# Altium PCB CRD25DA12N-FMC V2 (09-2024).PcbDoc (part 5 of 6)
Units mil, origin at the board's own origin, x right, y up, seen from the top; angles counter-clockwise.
Board outline 8000 x 8000 mil, 6 copper layers (Top Layer, Layer 2, Layer 3, Layer 4, Layer 5, Bottom Layer), stack 91 mil thick; 602 components, 333 nets, 1670 pads, 639 vias.
Unrouted connection lines stored in the file: 1.
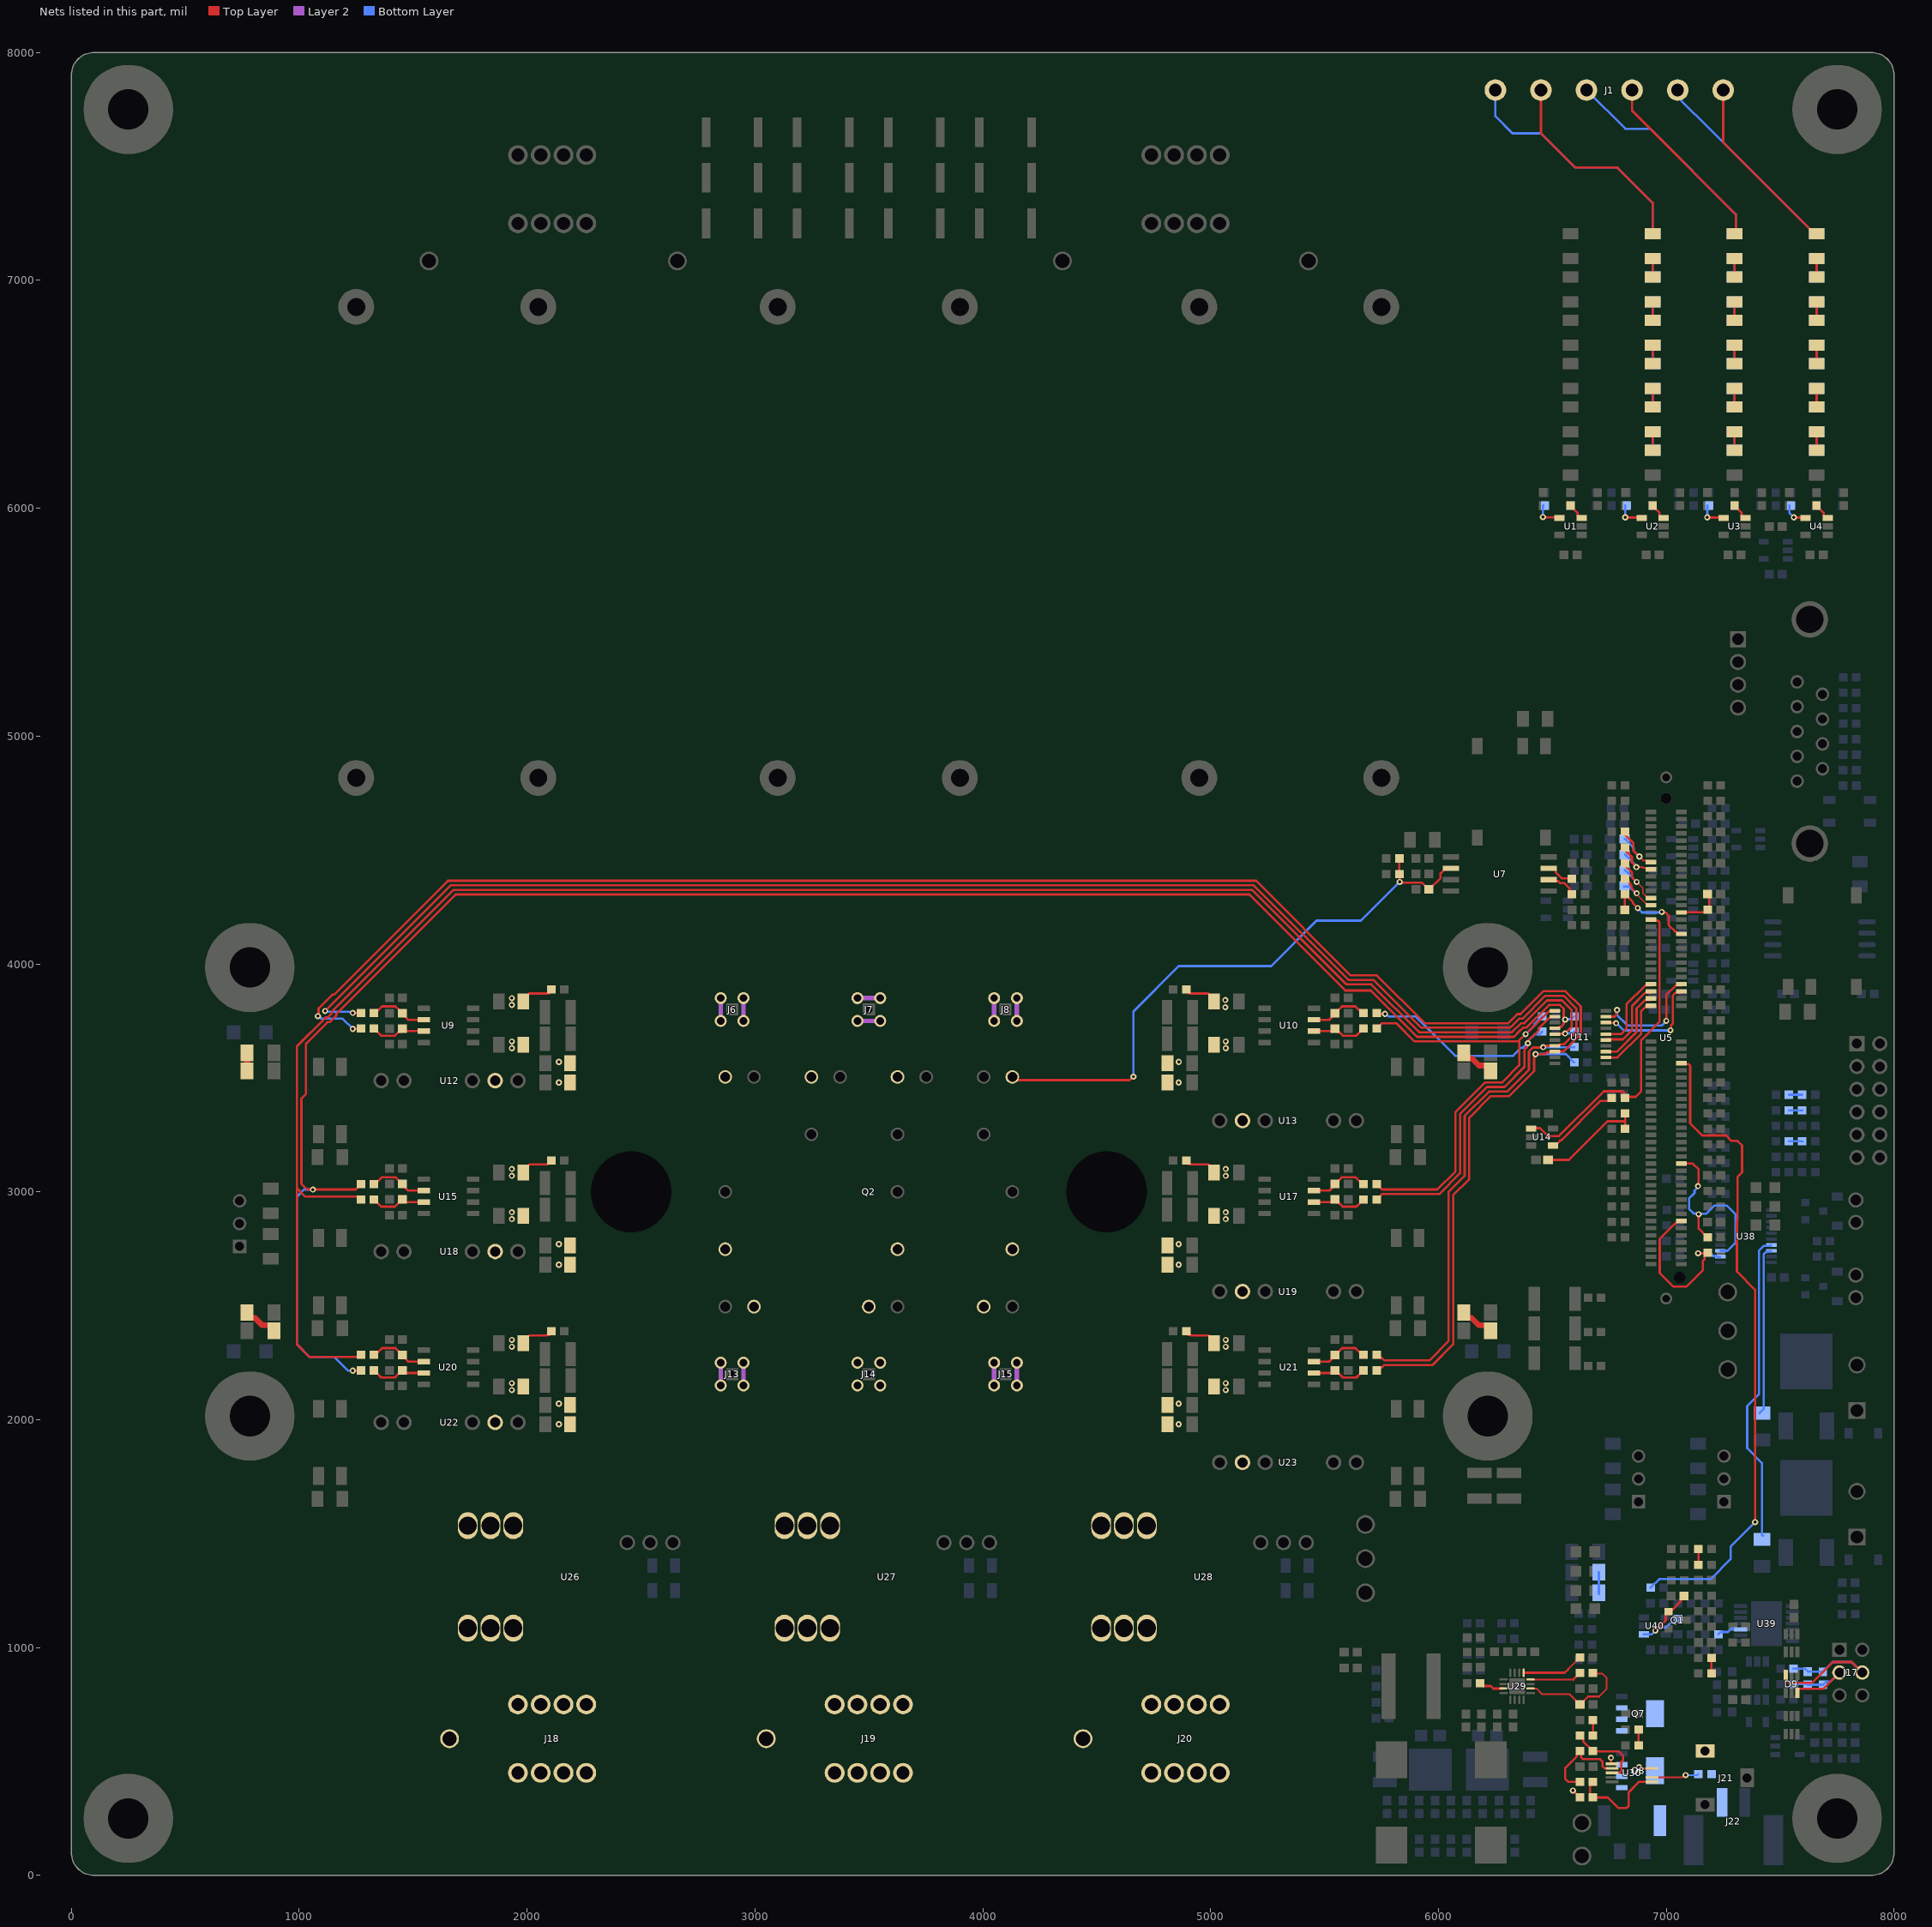
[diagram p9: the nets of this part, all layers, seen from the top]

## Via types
v1: diameter 27, hole 13, Top Layer to Bottom Layer, tented both sides, 543 vias
v2: diameter 50, hole 28, Top Layer to Bottom Layer, tented both sides, 76 vias
v3: diameter 19.68, hole 7.87, Top Layer to Bottom Layer, tented top, 15 vias
v4: diameter 19.68, hole 7.87, Top Layer to Bottom Layer, tented both sides, 5 vias

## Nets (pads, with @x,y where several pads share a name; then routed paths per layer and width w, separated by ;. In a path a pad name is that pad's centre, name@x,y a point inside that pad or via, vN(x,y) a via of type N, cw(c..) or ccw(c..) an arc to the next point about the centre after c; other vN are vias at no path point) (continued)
NetR14_2: R14.2 R18.1 | length 79.8
  Top Layer w10: R18.1@6940,7015.12 R14.2@6940,7094.88
NetR15_2: R15.2 R19.1 | length 79.8
  Top Layer w10: R19.1@7300,7015.12 R15.2@7300,7094.88
NetR16_2: R16.2 R20.1 | length 79.8
  Top Layer w10: R20.1@7660,7015.12 R16.2@7660,7094.88
NetR18_2: R18.2 R22.1 | length 79.8
  Top Layer w10: R22.1@6940,6825.12 R18.2@6940,6904.88
NetR19_2: R19.2 R23.1 | length 79.8
  Top Layer w10: R23.1@7300,6825.12 R19.2@7300,6904.88
NetR20_2: R20.2 R24.1 | length 79.8
  Top Layer w10: R24.1@7660,6825.12 R20.2@7660,6904.88
NetR22_2: R22.2 R26.1 | length 79.8
  Top Layer w10: R26.1@6940,6635.12 R22.2@6940,6714.88
NetR23_2: R23.2 R27.1 | length 79.8
  Top Layer w10: R27.1@7300,6635.12 R23.2@7300,6714.88
NetR24_2: R24.2 R28.1 | length 79.8
  Top Layer w10: R28.1@7660,6635.12 R24.2@7660,6714.88
NetR26_2: R26.2 R30.1 | length 79.8
  Top Layer w10: R30.1@6940,6445.12 R26.2@6940,6524.88
NetR27_2: R27.2 R31.1 | length 79.8
  Top Layer w10: R31.1@7300,6445.12 R27.2@7300,6524.88
NetR28_2: R28.2 R32.1 | length 79.8
  Top Layer w10: R32.1@7660,6445.12 R28.2@7660,6524.88
NetR30_2: R30.2 R34.1 | length 79.8
  Top Layer w10: R34.1@6940,6255.12 R30.2@6940,6334.88
NetR31_2: R31.2 R35.1 | length 79.8
  Top Layer w10: R35.1@7300,6255.12 R31.2@7300,6334.88
NetR32_2: R32.2 R36.1 | length 79.8
  Top Layer w10: R36.1@7660,6255.12 R32.2@7660,6334.88
NetR37_2: R37.2 U1.3 | length 79.1
  Top Layer w10: R37.2@6580,6011.38 6580,6010.47 6610.59,5979.88 6610.59,5966.18 6619.37,5957.4 U1.3@6628.23,5957.4
NetR39_2: R39.2 U2.3 | length 84.1
  Top Layer w10: R39.2@6940,6011.38 6940,6010.47 6970.59,5979.88 6970.59,5961.18 6979.37,5952.4 U2.3@6988.23,5952.4
NetR41_2: R41.2 U3.3 | length 79.1
  Top Layer w10: R41.2@7300,6011.38 7300,6010.47 7330.59,5979.88 7330.59,5966.18 7339.37,5957.4 U3.3@7348.23,5957.4
NetR43_2: R43.2 U4.3 | length 79.1
  Top Layer w10: R43.2@7660,6011.38 7660,6010.47 7690.59,5979.88 7690.59,5966.18 7699.37,5957.4 U4.3@7708.23,5957.4
NetR56_2: R56.2 U7.7 | length 122.2
  Top Layer w10: U7.7@6484.57,4420 6508.19,4420 6515,4413.19 6515,4402.37 6542.37,4375 6580.38,4375 R56.2@6581.38,4374
NetR58_2: R58.2 U7.6 | length 137.2
  Top Layer w10: U7.6@6484.57,4370 6491.38,4363.19 6525.89,4363.19 6534.08,4355 6552.56,4355 6574.96,4332.61 6574.96,4317.42 R58.2@6586.38,4306
NetR77_1: R77.1 R80.2 | length 81.7
  Top Layer w25: R80.2@770.9,3530 770.9,3605.9 R77.1@775,3610
NetR78_1: R78.1 R81.2 | length 158.9
  Top Layer w25: R78.1@6110.9,3610 6110.9,3602.08 6127.05,3585.92 6146.37,3585.92 6178.22,3554.08 6212.95,3554.08 6225,3542.03 R81.2@6225,3530
NetR85_2: R85.2 U14.4 | length 335.2
  Top Layer w10: U14.4@6512.09,3204.6 6514.09,3204.6 6534.49,3225 6538.28,3225 6712.33,3399.04 6748.42,3399.04 R85.2@6761.38,3412
NetR86_1: R86.1 R88.1 R91.1 | length 477.1
  Top Layer w10: R91.1@6481.62,3140 6573.01,3140 6742.32,3309.31 6820,3309.31 ; R86.1@6818.62,3344 6820,3342.62 6820,3309.31 ; R88.1@6820,3276 6820,3309.31
NetR115_2: R115.2 R118.1 | length 163.1
  Top Layer w25: R115.2@770.9,2470 770.9,2462.08 787.05,2445.92 806.37,2445.92 838.22,2414.08 872.95,2414.08 895,2392.03 R118.1@895,2390
NetR116_1: R116.1 R119.2 | length 159.8
  Top Layer w25: R116.1@6110.9,2470 6110.9,2462.08 6127.05,2445.92 6146.37,2445.92 6178.22,2414.08 6215.92,2414.08 R119.2@6235,2395
NetR136_2: R136.2 R137.1 | length 69
  Top Layer w10: R137.1@7141.38,1363 R136.2@7141.38,1432
NetR145_2: R145.2 U29.5 | length 274.5
  Top Layer w8: 6569.74,905.26 6620.47,956 R145.2@6621.38,956
  Top Layer w10: U29.5@6374.53,889.23 6553.71,889.23 6569.74,905.26
NetR146_1: R146.1 R148.2 | length 68
  Top Layer w10: R148.2@7198.62,886 R146.1@7198.62,954
NetR147_1: R147.1 U29.4 | length 228.9
  Top Layer w8: U29.4@6404.23,859.53 6592,859.53
  Top Layer w10: 6592,859.53 6620.47,888 R147.1@6621.38,888
NetR149_2: R149.2 U29.11 | length 112.3
  Top Layer w10: R149.2@6183.62,844 6196.58,831.04 6229.48,831.04 6240.69,819.84 6264.04,819.84 6285.48,819.87 U29.11@6285.77,820.16
NetR150_2: R150.2 R152.1 | length 72.5
  Top Layer w10: R150.2@6675,685 6678.62,681.38 R152.1@6678.62,614
NetR151_2: R151.2 R153.1 | length 70
  Top Layer w10: R153.1@6878.62,570 R151.2@6878.62,640
NetR152_2: R152.2 R154.1 U30.3 | length 348.4
  Top Layer w8: U30.3@6761.17,449.69 6795,449.69
  Top Layer w10: R152.2@6621.38,614 6622.28,614 6635.24,601.04 6635.24,588.48 6677.72,546 R154.1@6678.62,546 6679.94,544.68 6769.2,544.68 6770.38,543.5 6791.81,543.5 6810,525.31 6810,505 6803.1,498.1 6803.1,458.1 6795,450 6795,449.69
NetR154_2: R154.2 R155.1 U30.2 | length 418.9
  Top Layer w8: 6730,469.69 U30.2@6762.91,469.69
  Top Layer w10: R155.1@6621.38,410 6570,410 6556.5,423.5 6556.5,471.5 6580,495 6607.52,522.52 6607.52,533.04 R154.2@6620.47,546 ; R154.2@6621.38,546 R154.2@6620.47,546 ; 6730,469.69 6720,479.69 6720,500 6710,510 6635,510 6626.1,518.9 6626.1,536.38 6626.1,540.38 R154.2@6620.47,546
NetR155_2: R155.2 R156.1 U30.6 | length 442.1
  Top Layer w10: R156.1@6678.62,342 6743,342 6790,295 6825.31,295 6835,304.69 6835,365 6880.63,410.63 U30.6@6937.09,410.63 ; R155.2@6678.62,410 6677.96,410 6665,397.04 6665,354.96 6677.96,342 R156.1@6679.53,342
NetR157_2: R157.2 R161.1 | length 79.8
  Bottom Layer w10: R161.1@7660,7015.12 R157.2@7660,7094.88
NetR158_2: R158.2 R162.1 | length 79.8
  Bottom Layer w10: R162.1@7300,7015.12 R158.2@7300,7094.88
NetR159_2: R159.2 R163.1 | length 79.8
  Bottom Layer w10: R163.1@6940,7015.12 R159.2@6940,7094.88
NetR161_2: R161.2 R165.1 | length 79.8
  Bottom Layer w10: R165.1@7660,6825.12 R161.2@7660,6904.88
NetR162_2: R162.2 R166.1 | length 79.8
  Bottom Layer w10: R166.1@7300,6825.12 R162.2@7300,6904.88
NetR163_2: R163.2 R167.1 | length 79.8
  Bottom Layer w10: R167.1@6940,6825.12 R163.2@6940,6904.88
NetR165_2: R165.2 R169.1 | length 79.8
  Bottom Layer w10: R169.1@7660,6635.12 R165.2@7660,6714.88
NetR166_2: R166.2 R170.1 | length 79.8
  Bottom Layer w10: R170.1@7300,6635.12 R166.2@7300,6714.88
NetR167_2: R167.2 R171.1 | length 79.8
  Bottom Layer w10: R171.1@6940,6635.12 R167.2@6940,6714.88
NetR169_2: R169.2 R173.1 | length 79.8
  Bottom Layer w10: R173.1@7660,6445.12 R169.2@7660,6524.88
NetR170_2: R170.2 R174.1 | length 79.8
  Bottom Layer w10: R174.1@7300,6445.12 R170.2@7300,6524.88
NetR171_2: R171.2 R175.1 | length 79.8
  Bottom Layer w10: R175.1@6940,6445.12 R171.2@6940,6524.88
NetR173_2: R173.2 R177.1 | length 79.8
  Bottom Layer w10: R177.1@7660,6255.12 R173.2@7660,6334.88
NetR174_2: R174.2 R178.1 | length 79.8
  Bottom Layer w10: R178.1@7300,6255.12 R174.2@7300,6334.88
NetR175_2: R175.2 R179.1 | length 79.8
  Bottom Layer w10: R179.1@6940,6255.12 R175.2@6940,6334.88
NetR182_2: R182.2 U4.4 | length 112.5
  Top Layer w10: v1(7560,5960) 7561.3,5958.7 7610.47,5958.7 U4.4@7611.77,5957.4
  Bottom Layer w10: R182.2@7540,6011.38 7540,5980 v1(7560,5960)
NetR185_2: R185.2 U3.4 | length 124.2
  Top Layer w10: v1(7180,5960) 7181.3,5958.7 7250.47,5958.7 U3.4@7251.77,5957.4
  Bottom Layer w10: v1(7180,5960) R185.2@7180,6011.38
NetR188_2: R188.2 U2.4 | length 124.2
  Top Layer w10: v1(6820,5960) 6821.3,5958.7 6890.47,5958.7 U2.4@6891.77,5957.4
  Bottom Layer w10: v1(6820,5960) R188.2@6820,6011.38
NetR191_2: R191.2 U1.4 | length 125.4
  Top Layer w10: v1(6458.58,5961.42) 6460.59,5959.41 6529.76,5959.41 U1.4@6531.77,5957.4
  Bottom Layer w10: v1(6458.58,5961.42) 6458.58,6009.96 R191.2@6460,6011.38
NetR221_2: R221.2 R222.1 | length 57.8
  Bottom Layer w10: R222.1@7538.62,3426 R221.2@7596.38,3426
NetR224_2: R224.2 R225.1 | length 57.8
  Bottom Layer w10: R225.1@7538.62,3358 R224.2@7596.38,3358
NetR230_2: R230.2 R231.1 | length 62.2
  Bottom Layer w8: R231.1@7538.62,3222 R230.2@7596.38,3222 7598,3222 R230.2@7600,3220
NetR246_1: R246.1 R248.2 | length 95.4
  Bottom Layer w10: R246.1@6704.1,1330 R248.2@6704.1,1240 6704.1,1235.9 R248.2@6705,1235
NetR257_1: R257.1 U39.3 | length 76.6
  Bottom Layer w10: R257.1@7228.62,1058 7238.6,1067.98 7271.26,1067.98 7286.55,1083.27 7294.76,1083.27
NetR275_1: R275.1 U30.7 | length 210.4
  Top Layer w8: U30.7@6937.09,430.32 7070.17,430.32 7079.86,440 v1(7085,440)
  Bottom Layer w8: v1(7085,440) 7136.38,440 R275.1@7141.38,445
NTC1: C18.1 Q2.NTC2 R53.1 R55.2 U7.2 | length 2627.4
  Top Layer w10: Q2.NTC2@4129.92,3503.94 4143.45,3503.94 4157.39,3490 4645.4,3490 4660.4,3505 v1(4661.5,3505) ; R53.1@5828.62,4463 R55.2@5828.62,4395 5830,4393.62 v1(5830,4360) 5833.14,4356.86 5927.76,4356.86 5957.63,4327 C18.1@5958.58,4327 5959.53,4327 6009,4376.47 6009,4397.19 6031.81,4420 U7.2@6055.43,4420
  Bottom Layer w10: v1(4661.5,3505) 4661.5,3791.5 4860.75,3990.75 5265.75,3990.75 5465,4190 5660,4190 v1(5830,4360)
NTC_ISO: C21.1 R59.2 U5.36 | length 414.7
  Top Layer w10: C21.1@6818.58,4240 R59.2@6818.62,4306 R59.2@6818.62,4306 6819.53,4306 6854.08,4271.45 6854.08,4265.92 v1(6875,4245) ; v1(6980.19,4228.29) 6984.79,4228.29 6988.08,4225 6997.19,4225 7011.1,4211.09 7011.1,4170 7038.75,4142.35 7042.5,4142.35 7053.15,4131.69 U5.36@7066.93,4131.69
  Bottom Layer w10: v1(6875,4245) 6893.91,4226.09 v1@6980.19,4226.09
RELAY1: R244.1 U38.17 | length 1364.6
  Bottom Layer w10: R244.1@7425,1490 7420,1495 7420,1810 7355,1875 7355,2060 7407.58,2112.58 7407.58,2742.42 7428.03,2762.87 7456.69,2762.87 U38.17@7459.41,2765.59
RELAY1_OUT: R111.2 U5.92 U38.3 | length 847.1
  Top Layer w10: U5.92@7066.93,3123.82 7116.18,3123.82 7141.99,3098.01 7141.99,3027.86 v1(7139.23,3025.1) ; v1(7142.17,2901.43) 7141.81,2901.06 7141.81,2838.67 7180.47,2800 R111.2@7181.38,2800
  Bottom Layer w10: v1(7139.23,3025.1) 7139.23,3020.5 7123.63,3004.91 7123.63,2993.33 7121.81,2991.5 7120.99,2991.5 7099.95,2970.46 7099.95,2924.75 7120.02,2904.68 7138.92,2904.68 v1(7142.17,2901.43) ; v1@7142.17,2900 7146.1,2903.93 7175.67,2903.93 7211.9,2940.16 7264.84,2940.16 7304.04,2900.96 7304.04,2777.07 7267.99,2741.02 U38.3@7237.8,2741.02
RELAY2: R243.1 U38.18 | length 742.2
  Bottom Layer w10: R243.1@7410,2029.1 7427.58,2046.69 7427.58,2726.71 7435.18,2734.31 7439.74,2734.31 7443.58,2738.15 7457.56,2738.15 U38.18@7459.41,2740
RELAY2_OUT: R112.2 U5.108 U38.2 | length 744.3
  Top Layer w10: U5.108@7066.93,2871.85 7053.15,2871.85 7042.5,2861.2 7038.75,2861.2 6971.5,2793.95 6971.5,2643.5 7031.18,2583.82 7088.82,2583.82 7160,2655 7160,2695.31 7167.52,2702.82 7167.52,2719.04 R112.2@7178.47,2730 ; v1(7140,2730) R112.2@7178.47,2730 ; R112.2@7179.38,2730 R112.2@7178.47,2730
  Bottom Layer w10: v1(7140,2730) 7194.6,2730 7206.29,2718.31 7219.17,2718.31 7223.07,2714.41 U38.2@7235,2714.41
RSLV_PWM: R247.1 U5.64 | length 2869.7
  Top Layer w10: U5.64@7066.93,3564.76 7071.69,3560 7098.75,3560 7105,3553.75 7105,3300.01 7157.96,3247.04 7262.96,3247.04 7286.5,3223.5 7312.79,3223.5 7332.57,3203.72 7332.57,3085.27 7313.5,3066.21 7313.5,2877.28 7310,2873.78 7310,2650 7390,2570 v1(7390,1550)
  Bottom Layer w10: R247.1@6931.38,1263 6932.28,1263 6969.17,1299.89 7194.89,1299.89 7282.19,1387.19 7282.19,1442.19 v1(7390,1550)
RSLV_PWM_FILT: C91.1 Q1.1 R253.2 U40.1 | length 383.9
  Top Layer w10: v1(6952.26,1074.16) 6997.91,1119.81 6997.91,1146.65 7008.66,1157.4 Q1.1@7010.63,1157.4 ; Q1.1@7015.63,1157.4 7017.6,1157.4 7063.76,1203.57 7063.76,1213.14 7077.63,1227 C91.1@7078.58,1227
  Bottom Layer w10: U40.1@6901.77,1057.6 6935.7,1057.6 v1(6952.26,1074.16) 6956.86,1074.16 6970.8,1088.1 7000.44,1088.1 7019.3,1106.96 7031.43,1106.96 7050.47,1126 R253.2@7051.38,1126
S1: C51.1 C59.2 C65.1 C67.2 J6.2 J6.3 J6.4 J6.5 Q2.S1 R94.1 U18.6 | length 346.1
  Top Layer w10: C51.1@1984.19,3085 1984.19,3093.91 2010.28,3120 2087.47,3120 2097.47,3130 R94.1@2106.38,3130
  Layer 2 w20: J6.4@2850,3750 J6.2@2850,3850 ; J6.5@2950,3750 J6.3@2950,3850
  other v1: 2140,2680 2140,2770 1933.37,2880 1933.37,2910 1933.37,3070 1933.37,3100
S2: C73.1 C79.2 C83.1 C85.2 J13.2 J13.3 J13.4 J13.5 Q2.S2 R120.1 U22.6 | length 346.1
  Top Layer w10: C73.1@1984.19,2335 1984.19,2343.91 2010.28,2370 2086.66,2370 2088.7,2372.04 2098.42,2372.04 R120.1@2106.38,2380
  Layer 2 w20: J13.4@2850,2150 J13.2@2850,2250 ; J13.5@2950,2150 J13.3@2950,2250
  other v1: 2140,1980 2140,2070 1933.37,2130 1933.37,2160 1933.37,2320 1933.37,2350
S3: C28.1 C36.2 C40.1 C42.2 J7.2 J7.3 J7.4 J7.5 Q2.S3 R64.1 U12.6 | length 346.1
  Top Layer w10: C28.1@1984.19,3835 1984.19,3843.91 2010.28,3870 2086.66,3870 2088.7,3872.04 2098.42,3872.04 R64.1@2106.38,3880
  Layer 2 w20: J7.4@3450,3750 J7.5@3550,3750 ; J7.2@3450,3850 J7.3@3550,3850
  other v1: 2140,3480 2140,3570 1933.37,3630 1933.37,3660 1933.37,3820 1933.37,3850
S4: C74.2 C80.1 C84.1 C86.2 J14.2 J14.3 J14.4 J14.5 Q2.S4 R121.1 U23.6 | length 146.1
  Top Layer w10: R121.1@4893.62,2380 4901.58,2372.04 4911.3,2372.04 4913.34,2370 4989.72,2370 5015.81,2343.91 C74.2@5015.81,2335
  other v1: 4860,1980 4860,2070 5066.63,2130 5066.63,2160 5066.63,2320 5066.63,2350
S5: C29.2 C37.1 C41.1 C43.2 J8.2 J8.3 J8.4 J8.5 Q2.S5 R65.1 U13.6 | length 346.1
  Top Layer w10: R65.1@4893.62,3880 4901.58,3872.04 4911.3,3872.04 4913.34,3870 4989.72,3870 5015.81,3843.91 C29.2@5015.81,3835
  Layer 2 w20: J8.4@4050,3750 J8.2@4050,3850 ; J8.5@4150,3750 J8.3@4150,3850
  other v1: 4860,3480 4860.39,3569.95 5066.63,3630 5066.63,3660 5065,3810 5065,3841.5
S6: C52.2 C60.1 C66.1 C68.2 J15.2 J15.3 J15.4 J15.5 Q2.S6 R95.1 U19.6 | length 346.1
  Top Layer w10: R95.1@4893.62,3130 4901.58,3122.04 4911.3,3122.04 4913.34,3120 4989.72,3120 5015.81,3093.91 C52.2@5015.81,3085
  Layer 2 w20: J15.4@4050,2150 J15.2@4050,2250 ; J15.5@4150,2150 J15.3@4150,2250
  other v1: 4860,2680 4860,2770 5066.63,2880 5066.63,2910 5066.63,3070 5066.63,3100
SIN: C19.1 R60.2 U5.30 | length 184.6
  Top Layer w10: U5.30@7066.93,4226.18 7171.56,4226.18 R60.2@7181.38,4236 ; R60.2@7187.44,4240 7188.72,4241.28 7188.72,4303.72 C19.1@7190,4305
SIN_N: C173.2 D9.6 J17.4 R264.1 R265.1 | length 767.9
  Top Layer w10: D9.6@7524.41,879.37 7528.27,875.51 7528.27,854.05 7536.59,845.73 7640.73,845.73 7731.5,936.5 7813.5,936.5 J17.4@7860,890
  Bottom Layer w10: R264.1@7558.62,907 7609.53,907 C173.2@7622,894.53 ; C173.2@7622,893.58 7689.96,893.58 R265.1@7689.96,896.48 ; R265.1@7688,893.62 7688,894.53 R265.1@7689.96,896.48 ; J17.4@7860,890 7813.5,936.5 7729.97,936.5 R265.1@7689.96,896.48
SIN_P: C173.1 D9.3 J17.3 R265.2 R267.1 | length 454.7
  Top Layer w10: D9.3@7575.59,800.63 7575.59,814.41 7579.45,818.27 7688.27,818.27 J17.3@7760,890
  Bottom Layer w10: R267.1@7558.62,839 7619.42,839 7622,836.42 R265.2@7688,836.38 7688,837.28 7700.96,850.24 7720.24,850.24 J17.3@7760,890
T_AMB: R85.1 U5.31 U14.1 | length 1431.3
  Top Layer w10: U14.1@6406.77,3279.4 6445.6,3279.4 6480,3245 6530,3245 6725.96,3440.96 6809.04,3440.96 6815,3435 6815,3415.62 R85.1@6818.62,3412 6823.39,3416.76 6865.74,3416.76 6890,3441.02 6890,3665.2 6970,3745.2 6970,4183.75 6963.75,4190 6937.76,4190 U5.31@6933.07,4194.68
U: Q2.U U26.4 U26.5 U26.6
U_HS: R99.1 R129.1 R214.2 U11.14 | length 8252.6
  Top Layer w10: v1(1235,2215) 1270.38,2215 R129.1@1271.38,2216 ; R99.1@1271.38,3034 1270.47,3034 1257.52,3021.04 1257.52,3020.14 1247.38,3010 v1(1060,3010) 1035,3010 1010,3035 1010,3410 1030,3430 1030,3650 1124.69,3744.69 1133.59,3744.69 1162,3773.11 1162,3780.43 1686.57,4305 5170,4305 5591.64,3883.36 5703.36,3883.36 5906.72,3680 6331.11,3680 6355.11,3704 6371.11,3720 6385.17,3720 6485.17,3820 6533.43,3820 6550,3803.43 v1@6550,3755 ; U11.14@6510.59,3717.36 6526.34,3717.36 6533.06,3724.08 6537.62,3724.08 6550,3736.46 v1@6550,3755 ; v1(6556.77,3755.76) 6550.76,3755.76 v1@6550,3755
  Bottom Layer w10: v1(1060,3010) 1021.65,3010 990,2978.35 990,2330 1045,2275 1155,2275 1215,2215 v1(1235,2215) ; v1(6556.77,3755.76) 6558.05,3757.04 6583.42,3757.04 R214.2@6596.38,3770
U_HS+_FILT: C54.1 R99.2 U15.2 | length 256.7
  Top Layer w10: R99.2@1328.62,3034 1341.58,3046.96 1346.96,3046.96 1363.86,3063.86 1422.76,3063.86 1438.76,3047.86 1449.53,3037.1 1449.53,3034 1478.53,3005 U15.2@1546.73,3005
U_HS-_FILT: C77.1 R129.2 U20.3 | length 258
  Top Layer w10: R129.2@1328.62,2216 1329.53,2216 1342.48,2203.04 1342.48,2202.52 1360,2185 1420,2185 1437.14,2202.14 1447.14,2202.14 1453.58,2208.58 C77.1@1453.58,2216 ; C77.1@1448.58,2216 1454.79,2209.79 1459.58,2205 U20.3@1546.73,2205
U_HS_PWM: U5.49 U11.6 | length 353.2
  Top Layer w10: U11.6@6735,3691.77 6801.77,3691.77 6825,3715 6825,3822.63 6906.98,3904.61 6930.16,3904.61 U5.49@6935,3909.45
U_LS: R103.1 R126.1 R216.2 U11.15 | length 8340.8
  Top Layer w10: R126.1@1271.38,2284 1262.38,2275 1045,2275 990,2330 990,3015 ; R103.1@1271.38,2966 1258.42,2978.96 1026.04,2978.96 990,3015 ; U11.15@6510.59,3691.77 6512.2,3693.39 6554.37,3693.39 6585.27,3724.28 6585.27,3796.45 6541.72,3840 6476.89,3840 6376.89,3740 6362.82,3740 6322.82,3700 5915,3700 5705,3910 5596.72,3910 5181.72,4325 1678.28,4325 1142,3788.72 1142,3781.39 1125.31,3764.69 1116.41,3764.69 990,3638.28 990,3015
  Bottom Layer w10: v1(6555.98,3695) 6588.38,3695 R216.2@6596.38,3703
U_LS+_FILT: C75.1 R126.2 U20.2 | length 256.7
  Top Layer w10: R126.2@1328.62,2284 1341.58,2296.96 1346.96,2296.96 1363.86,2313.86 1422.76,2313.86 1438.76,2297.86 1449.53,2287.1 1449.53,2284 1478.53,2255 U20.2@1546.73,2255
U_LS-_FILT: C57.1 R103.2 U15.3 | length 258
  Top Layer w10: R103.2@1328.62,2966 1329.53,2966 1342.48,2953.04 1342.48,2952.52 1360,2935 1420,2935 1437.14,2952.14 1447.14,2952.14 1453.58,2958.58 C57.1@1453.58,2966 ; C57.1@1448.58,2966 1454.79,2959.79 1459.58,2955 U15.3@1546.73,2955
U_LS_PWM: U5.51 U11.5 | length 349.9
  Top Layer w10: U11.5@6735,3666.18 6737.72,3668.9 6808.84,3668.9 6850,3710.05 6850,3816.13 6906.98,3873.11 6930.16,3873.11 U5.51@6935,3877.95
U_OUT: J18.1 J18.2 J18.3 J18.4 J18.5 J18.6 J18.7 J18.8 TP11.1 U26.1 U26.2 U26.3
V: Q2.V U27.4 U27.5 U27.6
V_HS: R69.1 R127.1 R218.2 U11.17 | length 8531.2
  Top Layer w10: v1(1113.5,3793.19) 1665.31,4345 5190,4345 5605,3930 5715,3930 5925,3720 6314.54,3720 6354.54,3760 6368.6,3760 6468.6,3860 6550,3860 6605.27,3804.73 6605.27,3700.27 6552.31,3647.31 6533.06,3647.31 6526.34,3640.59 U11.17@6510.59,3640.59 6470.19,3640.59 6464.6,3635 v1@6460,3635 ; v1(1235,3785) 1270.38,3785 R69.1@1271.38,3784 ; R127.1@5728.62,2284 5741.58,2271.04 5751.58,2271.04 5762.62,2260 5960,2260 6045,2345 6045,3000 6115,3070 6115,3333.43 6221.57,3440 6301.72,3440 6397.35,3535.64 6397.35,3615.78 6414.9,3633.33 6458.6,3633.33 v1(6459.74,3634.47)
  Bottom Layer w10: v1(1113.5,3793.19) 1116.69,3790 1220.64,3790 1222.39,3788.25 1231.75,3788.25 v1(1235,3785) ; v1(6459.74,3634.47) 6594.85,3634.47 R218.2@6596.38,3636
V_HS+_FILT: C32.1 R69.2 U9.2 | length 256.7
  Top Layer w10: R69.2@1328.62,3784 1341.58,3796.96 1346.96,3796.96 1363.86,3813.86 1422.76,3813.86 1438.76,3797.86 1449.53,3787.1 1449.53,3784 1478.53,3755 U9.2@1546.73,3755
V_HS-_FILT: C76.1 R127.2 U21.3 | length 256.7
  Top Layer w10: U21.3@5453.27,2255 5521.47,2255 5550.47,2284 5550.47,2287.1 5561.24,2297.86 5577.24,2313.86 5636.14,2313.86 5653.04,2296.96 5658.42,2296.96 R127.2@5671.38,2284
V_HS_PWM: U5.53 U11.3 | length 356.1
  Top Layer w10: U11.3@6735,3615 6783.23,3615 6870,3701.77 6870,3804.64 6906.98,3841.61 6930.16,3841.61 U5.53@6935,3846.46
V_LS: R72.1 R130.1 R219.2 U11.18 | length 8761.6
  Top Layer w10: v1(1082.04,3770.63) 1085,3773.59 1085,3805 1145,3865 1152.66,3865 1652.66,4365 5200,4365 5615,3950 5730,3950 5940,3740 6306.26,3740 6346.26,3780 6360.32,3780 6460.32,3880 6558.28,3880 6625.27,3813.02 6625.27,3691.98 6549.21,3615.93 6511.52,3615.93 6507.72,3612.13 6477.43,3612.13 6469.28,3603.98 v1@6426.71,3603.98 ; v1(1235,3715) 1270.38,3715 R72.1@1271.38,3716 ; R130.1@5728.62,2216 5741.58,2228.96 5751.58,2228.96 5762.62,2240 5975,2240 6065,2330 6065,2985 6135,3055 6135,3325.15 6229.85,3420 6310,3420 6420,3530 6420,3589.62 6422.6,3592.22 6422.6,3600.73 v1(6425.85,3603.98)
  Bottom Layer w10: v1(1082.04,3770.63) 1086.64,3770.63 1097.27,3760 1190,3760 v1(1235,3715) ; v1(6425.85,3603.98) 6426.87,3605 6558.47,3605 6595.47,3568 R219.2@6596.38,3568
V_LS+_FILT: C78.1 R130.2 U21.2 | length 258
  Top Layer w10: U21.2@5453.27,2205 5540.42,2205 5545.21,2209.79 C78.1@5551.42,2216 ; C78.1@5546.42,2216 5546.42,2208.58 5552.86,2202.14 5562.86,2202.14 5580,2185 5640,2185 5657.52,2202.52 5657.52,2203.04 5670.47,2216 R130.2@5671.38,2216
V_LS-_FILT: C34.1 R72.2 U9.3 | length 258
  Top Layer w10: R72.2@1328.62,3716 1329.53,3716 1342.48,3703.04 1342.48,3702.52 1360,3685 1420,3685 1437.14,3702.14 1447.14,3702.14 1453.58,3708.58 C34.1@1453.58,3716 ; C34.1@1448.58,3716 1454.79,3709.79 1459.58,3705 U9.3@1546.73,3705
V_LS_PWM: U5.55 U11.2 | length 351.8
  Top Layer w10: U11.2@6735,3589.41 6785.92,3589.41 6890,3693.49 6890,3793.14 6908.75,3811.89 6931.93,3811.89 U5.55@6935,3814.96
V_OUT: J19.1 J19.2 J19.3 J19.4 J19.5 J19.6 J19.7 J19.8 TP12.1 U27.1 U27.2 U27.3
VCC: C103.1 R147.2 U29.2 | length 507.7
  Top Layer w8: U29.2@6404.23,820.16 6429.84,820.16 6455,795 6575.47,795 6620.47,750 C103.1@6621.42,750 6622.37,750 6657.37,785 6705,785 6737.5,817.5 6737.5,867.5 6719.8,885.2 6681.42,885.2 R147.2@6678.62,888
VDC_MEAS: C134.1 R57.2 U5.27 | length 242.6
  Top Layer w6.5: v1(6870,4310) 6870,4305.7 6905.62,4270.08 6906.89,4270.08 6912.7,4264.27 6926.48,4264.27 U5.27@6933.07,4257.68
  Top Layer w10: R57.2@6818.62,4374 6819.53,4374 6836.84,4356.68 6838.32,4356.68 6841.5,4353.5 6841.5,4348.19 6847.73,4341.96 6847.73,4332.27 v1(6870,4310)
  Bottom Layer w10: C134.1@6815,4340 6837.47,4340 6837.47,4337.96 6865.43,4310 v1(6870,4310)
VIN: J21.1 J22.2 Q7.5 R156.2 R275.2 U30.1 | length 75.3
  Top Layer w10: v1(6590.28,371.98) 6590.49,371.98 6620.47,342 R156.2@6621.38,342 ; v1(6757.39,516.18) 6757.39,490.27 6758.3,489.37 U30.1@6762.91,489.37
VIN_MID: Q7.1 Q7.2 Q7.3 Q8.1 Q8.2 Q8.3
VIN_PROTECT: Q8.5 R276.1 U30.9 | length 57.5
  Top Layer w8: v1(6880.91,474.71) 6886.06,474.71 6891.82,468.94 6915.68,468.94 6915.68,468.84 U30.9@6935.93,468.84
VU_MEAS: C125.1 R51.2 U5.15 | length 302.6
  Top Layer w6.5: v1(6882.17,4471.22) 6900.14,4453.25 6926.48,4453.25 U5.15@6933.07,4446.65
  Top Layer w10: R51.2@6808.54,4577.05 6821.26,4564.33 6821.26,4564.27 6855.7,4529.83 6855.7,4497.69 v1(6882.17,4471.22)
  Bottom Layer w10: C125.1@6817.55,4548 6820.43,4548 6835.36,4533.08 6835.36,4530.19 6856.36,4509.19 6856.36,4497.03 v1(6882.17,4471.22)
VU_N: J1.2 R157.1 | length 888.5
  Bottom Layer w10: J1.2@7050,7835 7066.17,7818.83 7066.17,7788.83 7190,7665 7190.28,7665 7650.16,7205.12 R157.1@7660,7205.12
VU_P: J1.1 R16.1 | length 805.5
  Top Layer w10: J1.1@7250,7835 7250,7605.28 7650.16,7205.12 R16.1@7660,7205.12
VV_MEAS: C127.1 R52.2 U5.17 | length 246.3
  Top Layer w6.5: v1(6868.86,4425) 6893.89,4425 6897.14,4421.75 6926.48,4421.75 U5.17@6933.07,4415.16
  Top Layer w10: R52.2@6813.53,4505 6849.04,4469.48 6849.04,4445.49 6868.86,4425.68 v1(6868.86,4425)
  Bottom Layer w10: C127.1@6820.43,4480 6825.43,4475 6835.36,4465.08 6835.36,4462.19 6868.86,4428.69 v1(6868.86,4425)
VV_N: J1.4 R158.1 | length 967.7
  Bottom Layer w10: J1.4@6650,7835 6820,7665 6930,7665 7305,7290 7305,7210.12 R158.1@7300,7205.12
VV_P: J1.3 R15.1 | length 820.4
  Top Layer w10: J1.3@6850,7835 6850,7745 7305,7290 7305,7210.12 R15.1@7300,7205.12
VW_MEAS: C129.1 R54.2 U5.25 | length 270.3
  Top Layer w6.5: v1(6870,4360) 6896.75,4333.25 6896.75,4310.44 6905.62,4301.58 6906.89,4301.58 6919.29,4289.17 U5.25@6933.07,4289.17
  Top Layer w10: R54.2@6821.53,4430 6849.62,4401.91 6849.62,4380.38 v1(6870,4360)
  Bottom Layer w10: C129.1@6817.55,4411 6820.43,4411 6835.36,4396.08 6835.36,4394.64 v1(6870,4360)
VW_N: J1.6 R159.1 | length 1097.3
  Bottom Layer w10: J1.6@6250,7835 6250,7720 6325,7645 6450,7645 6600,7495 6785,7495 6940,7340 R159.1@6940,7205.12
VW_P: J1.5 R14.1 | length 941.2
  Top Layer w10: J1.5@6450,7835 6450,7645 6600,7495 6785,7495 6940,7340 R14.1@6940,7205.12
W: Q2.W U28.4 U28.5 U28.6
W_HS: R73.1 R100.1 R215.2 U11.11 | length 2115.8
  Top Layer w10: R100.1@5728.62,3034 5729.53,3034 5742.48,3021.04 5742.48,3020.14 5752.62,3010 5995,3010 6075,3090 6075,3350 6205,3480 6280,3480 6355,3555 6355,3665 ; R73.1@5728.62,3716 5729.53,3716 5742.48,3728.96 5742.48,3729.86 5752.62,3740 5815,3740 5895,3660 6350,3660 6355,3665 ; v1(6382.91,3691.5) v1@6381.5,3691.5 ; U11.11@6510.59,3794.13 6507.72,3791.26 6484.71,3791.26 6384.95,3691.5 v1@6381.5,3691.5 ; 6355,3665 v1@6381.5,3691.5
  Bottom Layer w10: v1(6382.91,3691.5) 6420.72,3729.3 6420.72,3735.25 6455,3769.53 R215.2@6455,3770
W_HS+_FILT: C35.1 R73.2 U10.2 | length 258
  Top Layer w10: U10.2@5453.27,3705 5540.42,3705 5545.21,3709.79 C35.1@5551.42,3716 ; C35.1@5546.42,3716 5546.42,3708.58 5552.86,3702.14 5562.86,3702.14 5580,3685 5640,3685 5657.52,3702.52 5657.52,3703.04 5670.47,3716 R73.2@5671.38,3716
W_HS-_FILT: C55.1 R100.2 U17.3 | length 256.7
  Top Layer w10: U17.3@5453.27,3005 5521.47,3005 5550.47,3034 5550.47,3037.1 5561.24,3047.86 5577.24,3063.86 5636.14,3063.86 5653.04,3046.96 5658.42,3046.96 R100.2@5671.38,3034
W_HS_PWM: U5.50 U11.9 | length 539.8
  Top Layer w10: U11.9@6735,3768.54 6773.62,3768.54 6780.61,3775.53 6780.61,3795 v1(6783.87,3798.26) ; v1(7000,3750) 7000,3863.77 7040.83,3904.61 7064.02,3904.61 U5.50@7068.86,3909.45
  Bottom Layer w10: v1(6783.87,3798.26) 6783.87,3776.13 6830,3730 6980,3730 v1(7000,3750)
W_LS: R70.1 R104.1 R217.2 U11.12 | length 2183.7
  Top Layer w10: R104.1@5728.62,2966 5729.53,2966 5742.48,2978.96 5742.48,2979.86 5752.62,2990 6003.28,2990 6095,3081.72 6095,3341.72 6213.28,3460 6289.93,3460 6377.35,3547.43 6377.35,3624.07 6389.19,3635.91 6389.19,3648.62 v1(6392.44,3651.88) ; R70.1@5728.62,3784 5731.76,3780.86 v1(5765.55,3780.86) ; v1@6389.03,3655.37 v1@6392.28,3658.62 ; v1@6392.14,3660.42 6440.35,3708.63 6440.35,3718.61 6483.57,3761.83 6488.13,3761.83 6494.84,3768.54 U11.12@6510.59,3768.54
  Bottom Layer w10: v1(5765.55,3780.86) 5770.15,3780.86 5781.01,3770 5899.69,3770 6073.19,3596.5 6328.24,3596.5 6364.34,3632.6 6371.41,3632.6 6392.14,3653.33 v1@6392.14,3658.62 ; v1@6388.03,3656.29 v1(6392.44,3651.88) ; v1@6392.14,3660.42 6422.05,3690.33 6442.52,3690.33 6455,3702.81 R217.2@6455,3703
W_LS+_FILT: C58.1 R104.2 U17.2 | length 258
  Top Layer w10: U17.2@5453.27,2955 5540.42,2955 5545.21,2959.79 C58.1@5551.42,2966 ; C58.1@5546.42,2966 5546.42,2958.58 5552.86,2952.14 5562.86,2952.14 5580,2935 5640,2935 5657.52,2952.52 5657.52,2953.04 5670.47,2966 R104.2@5671.38,2966
W_LS-_FILT: C33.1 R70.2 U10.3 | length 256.7
  Top Layer w10: U10.3@5453.27,3755 5521.47,3755 5550.47,3784 5550.47,3787.1 5561.24,3797.86 5577.24,3813.86 5636.14,3813.86 5653.04,3796.96 5658.42,3796.96 R70.2@5671.38,3784
W_LS_PWM: U5.52 U11.8 | length 501.6
  Top Layer w10: U11.8@6735,3742.95 6736.54,3741.41 6778.29,3741.41 v1(6779.83,3739.87) ; v1(7018.47,3708.51) 7021.72,3711.76 7021.72,3731.42 7028.5,3738.19 7028.5,3860.78 7040.83,3873.11 7064.02,3873.11 U5.52@7068.86,3877.95
  Bottom Layer w10: v1(6779.83,3739.87) 6781.21,3739.87 6812.57,3708.51 v1(7018.47,3708.51)
W_OUT: J20.1 J20.2 J20.3 J20.4 J20.5 J20.6 J20.7 J20.8 TP13.1 U28.1 U28.2 U28.3
pads on no net: HS1.1 HS1.2 HS1.4 J4.1 J4.4 J4.6 J4.8 MH1.1 MH2.1 MH3.1 MH4.1 Q2.MH1 Q2.MH2 U5. U5.1 U5.2 U5.3 U5.4 U5.5 U5.6 U5.8 U5.12 U5.14 U5.18 U5.20 U5.21 U5.23 U5.24 U5.26 U5.28 U5.32 U5.40 U5.41 U5.42 U5.43 U5.44 U5.45 U5.54 U5.56 U5.57 U5.59 U5.61 U5.62 U5.63 U5.66 U5.67 U5.68 U5.69 U5.70 U5.71 U5.72 U5.73 U5.75 U5.76 U5.77 U5.78 U5.79 U5.80 U5.81 U5.82 U5.85 U5.86 U5.89 U5.91 U5.93 U5.104 U5.109 U5.110 U5.113 U5.114 U5.115 U5.116 U5.117 U5.118 U5.119 U5.121 U5.122 U6.8 U8.8 U11.13 U11.16 U29.15 U38.11 U38.12 U38.13 U38.14 U39.7 U39.8

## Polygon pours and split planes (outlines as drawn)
GND on Layer 2 "Layer 2-GND" (solid, pour order 2481): 112 vertices, not listed, extent 490,50 7950,6174.89
GND_NTC on Layer 2 "Layer 2-GND_NTC" (solid, pour order 2493): 17 vertices, not listed, extent 5750,4305 6200,5010
S1 on Layer 2 "Layer 2-S1" (solid, pour order 1856): 30 vertices, not listed, extent 1734.75,2630 3075,3875
S3 on Layer 2 "Layer 2-S3" (solid, pour order 2483): 30 vertices, not listed, extent 1735,3420 3555,4110
S5 on Layer 2 "Layer 2-S5" (solid, pour order 2086): 20 vertices, not listed, extent 3580,3440 4845,3860
S5 on Layer 2 "Layer 5-S4" (solid, pour order 2467): 4990,3880 4940,3880 4910,3910 4814.87,3910 ccw(c4815,3865) 4770,3865 4770,3449.84 ccw(c4815,3450) 4815,3405 4890,3405 5020,3275 5220.06,3275 ccw(c5220,3320) 5265,3320 5265,3825.1 ccw(c5220,3825) 5220,3870 5000,3870
GND_ISO on Layer 2 "Layer 2-GND_ISO" (solid, pour order 2419): 19 vertices, not listed, extent 7255,3810 7950,5585
DC+ on Layer 2 "Layer 2-DC+" (solid, pour order 2301): 4265,3185 4265,3259.86 ccw(c4210,3260) 4210,3315 2805,3315.04 2805,3312.91 ccw(c2790,3260) 2735,3260 2735,3185.09 ccw(c2790,3185) 2790,3130 4209.9,3130 ccw(c4210,3185)
DC- on Layer 2 "Layer 2-DC-" (solid, pour order 2108): 2790,2880 4209.9,2880 ccw(c4210,2935) 4265,2935.46 4265,2975 ccw(c4210,2975) 4210.01,3030 2789.63,3030 ccw(c2790,2975) 2735,2975 2735,2935.06 ccw(c2790,2935)
GND_NTC on Layer 2 "Layer 2-GND_NTC 1" (solid, pour order 2092): 4004.75,3445 4649.24,3445.01 ccw(c4649.99,3479.56) 4649.99,3445 ccw(c4649.99,3479.56) 4650,3445 ccw(c4650,3480) 4685,3480 4685,3495.01 ccw(c4650,3495) 4650.25,3530 4004.88,3530 ccw(c4005,3495) 3970,3495.19 3970,3480 ccw(c4005,3480)
S4 on Layer 2 "Layer 2-S4" (solid, pour order 1912): 24 vertices, not listed, extent 3425,1775 5265,2585
S2 on Layer 2 "Layer 2-S2" (solid, pour order 1838): 26 vertices, not listed, extent 1735,1930 3075,2585
S6 on Layer 2 "Layer 2-S6" (solid, pour order 208): 29 vertices, not listed, extent 3925,2120 5265,3160
W_OUT on Layer 2 "Layer 2-W_OUT" (solid, pour order 650): 25 vertices, not listed, extent 4325,340 5235,1620
V_OUT on Layer 2 "Layer 2-V_OUT" (solid, pour order 649): 25 vertices, not listed, extent 2935,340 3845,1620
U_OUT on Layer 2 "Layer 2-U_OUT" (solid, pour order 927): 25 vertices, not listed, extent 1545,340 2455,1620
+3.3V on Layer 4 "Layer 4-+3.3V" (solid, pour order 2455): 63 vertices, not listed, extent 6015,490 7950,6175
+12V on Layer 4 "Layer 3-+5V_ALT" (solid, pour order 1328): 20 vertices, not listed, extent 490,1590 1575,3890
DC+ on Layer 4 "Layer 4-DC+" (solid, pour order 1989): 50 vertices, not listed, extent 760,3125 6240.01,7740.1
-3V_V_HS on Layer 4 "Layer 4--3V_U_LS" (solid, pour order 2475): 1780,3430 2180.14,3430 ccw(c2180,3475) 2225,3475 2225,3865.14 ccw(c2180,3865) 2180,3910 1779.86,3910 ccw(c1780,3865) 1735,3865 1735,3474.86 ccw(c1780,3475)
-3V_U_HS on Layer 4 "Layer 4--3V_U_LS" (solid, pour order 2474): 1780,2680 2180.14,2680 ccw(c2180,2725) 2225,2725 2225,3115.14 ccw(c2180,3115) 2180,3160 1779.86,3160 ccw(c1780,3115) 1735,3115 1735,2724.86 ccw(c1780,2725)
+5V on Layer 4 "Layer 4-+5V 1" (solid, pour order 1716): 5960,1790 ccw(c5959.91,1835.09) 6005,1835 6005,3830 ccw(c5959.9,3829.9) 5960,3875 5630,3875 5470.31,3875 ccw(c5470.45,3829.55) 5425,3829.69 5425,1835 ccw(c5470.27,1835.27) 5470.31,1790
-3V_W_HS on Layer 4 "Layer 4--3V_V_LS" (solid, pour order 2463): 4990,3880 4940,3880 4910,3910 4814.87,3910 ccw(c4815,3865) 4770,3865 4770,3449.83 ccw(c4815,3450) 4815,3405 4890,3405 5020,3275 5220.06,3275 ccw(c5220,3320) 5265,3320 5265,3825.1 ccw(c5220,3825) 5220,3870 5000,3870
-3V_W_LS on Layer 4 "Layer 4--3V_V_LS" (solid, pour order 2462): 4990,3130 4940,3130 4910,3160 4814.87,3160 ccw(c4815,3115) 4770,3115 4770,2699.83 ccw(c4815,2700) 4815,2655 4890,2655 5020,2525 5220.06,2525 ccw(c5220,2570) 5265,2570 5265,3075.1 ccw(c5220,3075) 5220,3120 5000,3120
+5V_ISO on Layer 4 "Layer 4-+5V_ISO" (solid, pour order 2436): 32 vertices, not listed, extent 7255,3810 7950,5585
VIN on Layer 4 "Layer 4-VIN" (solid, pour order 1731): 6615,50 7245,50 ccw(c7245,120) 7315,120 7315,530 ccw(c7245,530) 7245,600 6615,600 ccw(c6615,530) 6545,530 6545,120 ccw(c6615,120)
+15V on Layer 4 "Layer 4-+15V" (solid, pour order 2253): 66 vertices, not listed, extent 2380,50 6905,2590
+15V on Layer 4 "Layer 4-+15V 1" (solid, pour order 2240): 6496.49,1263.51 ccw(c6540,1275) 6528.51,1231.49
U on Layer 4 "Bottom Layer-U" (solid, pour order 2033): 25 vertices, not listed, extent 1545,1000 2955,2845
V on Layer 4 "Bottom Layer-V" (solid, pour order 2030): 17 vertices, not listed, extent 2935,1000 3710,2845.01
W on Layer 4 "Bottom Layer-W" (solid, pour order 2029): 18 vertices, not listed, extent 4045,1000 4880,2845
-3V_V_LS on Layer 4 "Layer 4--3V_V_LS" (solid, pour order 1928): 4990,2380 4940,2380 4910,2410 4814.87,2410 ccw(c4815,2365) 4770,2365 4770,1949.83 ccw(c4815,1950) 4815,1905 4890,1905 5020,1775 5220.06,1775 ccw(c5220,1820) 5265,1820 5265,2325.1 ccw(c5220,2325) 5220,2370 5000,2370
-3V_U_LS on Layer 4 "Layer 4--3V_U_LS" (solid, pour order 1854): 1780,1930 2180.14,1930 ccw(c2180,1975) 2225,1975 2225,2365.14 ccw(c2180,2365) 2180,2410 1779.86,2410 ccw(c1780,2365) 1735,2365 1735,1974.86 ccw(c1780,1975)
+12V on Layer 3 "Layer 3-+12V" (solid, pour order 2246): 39 vertices, not listed, extent 5425,50 7950,4035
+15V on Layer 3 "Layer 3-+15V" (solid, pour order 2179): 7845,490 ccw(c7845,595) 7950,595 7950,1185 ccw(c7905,1185) 7905,1230 6909.9,1230 ccw(c6910,1185) 6865,1185 6865,534.97 ccw(c6910,535) 6910,490
+5V_ALT on Layer 3 "Layer 3-+5V_ALT" (solid, pour order 2478): 20 vertices, not listed, extent 490,1590 1575,3890
+5V on Layer 3 "Layer 3-+5V" (solid, pour order 2453): 52 vertices, not listed, extent 5975,1800 7950,6175
DC- on Layer 3 "Layer 3-DC-" (solid, pour order 1961): 57 vertices, not listed, extent 760,2878.55 6240,7740
+15V_V_HS on Layer 3 "Layer 3-+15V_U_LS" (solid, pour order 2477): 1780,3430 2180.14,3430 ccw(c2180,3475) 2225,3475 2225,3865.14 ccw(c2180,3865) 2180,3910 1779.86,3910 ccw(c1780,3865) 1735,3865 1735,3474.86 ccw(c1780,3475)
+15V_U_HS on Layer 3 "Layer 3-+15V_U_LS" (solid, pour order 2476): 1780,2680 2180.14,2680 ccw(c2180,2725) 2225,2725 2225,3115.14 ccw(c2180,3115) 2180,3160 1779.86,3160 ccw(c1780,3115) 1735,3115 1735,2724.86 ccw(c1780,2725)
+15V_W_LS on Layer 3 "Layer 3-+15V_V_LS" (solid, pour order 2461): 4990,3130 4940,3130 4910,3160 4814.87,3160 ccw(c4815,3115) 4770,3115 4770,2699.83 ccw(c4815,2700) 4815,2655 4890,2655 5020,2525 5220.06,2525 ccw(c5220,2570) 5265,2570 5265,3075.1 ccw(c5220,3075) 5220,3120 5000,3120
+15V_W_HS on Layer 3 "Layer 3-+15V_V_LS" (solid, pour order 2460): 4990,3880 4940,3880 4910,3910 4814.87,3910 ccw(c4815,3865) 4770,3865 4770,3449.83 ccw(c4815,3450) 4815,3405 4890,3405 5020,3275 5220.06,3275 ccw(c5220,3320) 5265,3320 5265,3825.1 ccw(c5220,3825) 5220,3870 5000,3870
+5V_ISO on Layer 3 "Layer 3-+5V_ISO" (solid, pour order 2437): 32 vertices, not listed, extent 7255,3810 7950,5585
-15V on Layer 3 "Layer 3--15V" (solid, pour order 2204): 46 vertices, not listed, extent 2380,50 6150,1515
V_OUT on Layer 3 "Layer 3-V_OUT" (solid, pour order 653): 3845,1015 3555,1305 3555,1475.39 ccw(c3410,1475) 3410,1620 3080.47,1620 ccw(c3079.99,1475.01) 2935,1475 2935,485 ccw(c3080,485) 3080,340 3699.83,340 ccw(c3700,485) 3845,485
+15V_V_LS on Layer 3 "Layer 3-+15V_V_LS" (solid, pour order 1925): 4990,2380 4940,2380 4910,2410 4814.87,2410 ccw(c4815,2365) 4770,2365 4770,1949.83 ccw(c4815,1950) 4815,1905 4890,1905 5020,1775 5220.06,1775 ccw(c5220,1820) 5265,1820 5265,2325.1 ccw(c5220,2325) 5220,2370 5000,2370
W_OUT on Layer 3 "Layer 3-W_OUT" (solid, pour order 830): 5235,1015 4945,1305 4945,1475.39 ccw(c4800,1475) 4800,1620 4470.24,1620 ccw(c4470,1475) 4325,1475 4325,485 ccw(c4470,485) 4470,340 5089.83,340 ccw(c5090,485) 5235,485
U_OUT on Layer 3 "Layer 3-U_OUT" (solid, pour order 1194): 2455,1015 2165,1305 2165,1475.39 ccw(c2020,1475) 2020,1620 1690.38,1620 ccw(c1689.99,1475.01) 1545,1475 1545,485 ccw(c1690,485) 1690,340 2309.83,340 ccw(c2310,485) 2455,485
+15V_U_LS on Layer 3 "Layer 3-+15V_U_LS" (solid, pour order 1847): 1780,1930 2180.14,1930 ccw(c2180,1975) 2225,1975 2225,2365.14 ccw(c2180,2365) 2180,2410 1779.86,2410 ccw(c1780,2365) 1735,2365 1735,1974.86 ccw(c1780,1975)
NetD13_2 on Bottom Layer "NONET_L-01_P-001" (solid, pour order 2514): 7900,2910 7710,2910 7710,2950 7650,2950 7650,2815 7900,2815
+12V on Bottom Layer "NONET_L-01_P-001" (solid, pour order 2513): 7900,3025 7900,2920 7710,2920 7710,3025
NetD14_2 on Bottom Layer "NONET_L-01_P-001" (solid, pour order 2405): 7900,2580 7710,2580 7710,2620 7650,2620 7650,2485 7900,2485
+12V on Bottom Layer "NONET_L-01_P-001" (solid, pour order 2404): 7900,2695 7900,2590 7710,2590 7710,2695
GND on Bottom Layer "Bottom Layer-GND 5" (solid, pour order 1670): 7470,1919.76 ccw(c7505,1919.76) 7505.14,1884.76 7600.14,1884.76 ccw(c7600,1919.76) 7635,1919.6 7635,2059.91 ccw(c7600,2059.77) 7600.18,2094.76 7504.81,2094.76 ccw(c7505,2059.77) 7470,2059.77
NetD17_2 on Bottom Layer "Bottom Layer-NetD17_2" (solid, pour order 1668): 18 vertices, not listed, extent 7470,1884.76 7950,2404.76
+12V on Bottom Layer "Bottom Layer-+12V 2" (solid, pour order 1669): 7875,1919.54 7875,2059.85 ccw(c7840,2059.76) 7840.15,2094.76 7789.82,2094.76 ccw(c7790,2059.77) 7755,2059.88 7755,1919.76 ccw(c7790,1919.76) 7789.87,1884.76 7840.18,1884.76 ccw(c7840,1919.76)
DC+ on Bottom Layer "Bottom Layer-DC+" (solid, pour order 2512): 47 vertices, not listed, extent 760,3180 6240.01,7740.1
S5 on Bottom Layer "Bottom Layer-S5" (solid, pour order 2027): 31 vertices, not listed, extent 4770,3275 5265,3910
NetC48_1 on Bottom Layer "NONET_L-01_P-001" (solid, pour order 2469): 5535,3365 ccw(c5535,3320) 5490,3320 5490,3230 ccw(c5535,3230) 5535,3185 5715,3185 cw(c5715,3140) 5760,3140 5760,3135 ccw(c5805,3135) 5805,3090 5925,3090 ccw(c5925,3135) 5970,3135 5970,3145.83 cw(c6004.58,3150.42) 6000,3185 ccw(c5992.08,3217.08) 6025,3220 6025,3320 ccw(c5980,3320) 5980,3365
NetC70_1 on Bottom Layer "NONET_L-01_P-001" (solid, pour order 2459): 5535,2615 ccw(c5535,2570) 5490,2570 5490,2480 ccw(c5535,2480) 5535,2435 5715,2435 cw(c5715,2390) 5760,2390 5760,2385 ccw(c5805,2385) 5805,2340 5925,2340 ccw(c5925,2385) 5970,2385 5970,2395.83 cw(c6004.58,2400.42) 6000,2435 ccw(c5992.08,2467.08) 6025,2470 6025,2570 ccw(c5980,2570) 5980,2615
NetC69_2 on Bottom Layer "Bottom Layer-NetC136_2" (solid, pour order 1108): 24 vertices, not listed, extent 1025,2340 1515.4,2790
GND on Bottom Layer "Bottom Layer-GND 4" (solid, pour order 1678): 6655,4275 6740.1,4275 ccw(c6740,4320) 6785,4319.97 6785,4685 ccw(c6739.93,4684.93) 6740.1,4730 6660,4730 ccw(c6660.07,4684.93) 6615,4685 6615,4315 ccw(c6655.02,4315.02)
GND on Bottom Layer "NONET_L-01_P-001" (solid, pour order 2409): 7300,485 7300,190 7170,190 7170,275 7065,275 7065,50 7515,50 7515,485
VIN on Bottom Layer "Bottom Layer-VIN" (solid, pour order 2408): 22 vertices, not listed, extent 6860,200 7290,830
GND_ISO on Bottom Layer "Bottom Layer-GND_ISO" (solid, pour order 774): 7795,4405 7885,4405 7885,4480.14 ccw(c7840,4480) 7840,4525 7839.82,4525 ccw(c7840,4480) 7795,4480 7795,4415
GND_ISO on Bottom Layer "Bottom Layer-GND_ISO 1" (solid, pour order 765): 7950,4155 7950,4290 7795,4290 7795,4200 ccw(c7840.07,4200.07) 7840,4155
+5V_ISO on Bottom Layer "+5V_ISO_L06_P517" (solid, pour order 517): 7795,4395 7795,4295 7910,4295 7910,4340 7885,4340 7885,4395
+5V_ISO on Bottom Layer "Bottom Layer-+5V_ISO" (solid, pour order 597): 7795,3855 ccw(c7840,3855) 7840,3810 7860,3810 7860,3940 7950,3940 7950,4020 ccw(c7904.94,4019.94) 7905,4065 7840,4065 ccw(c7840.01,4019.99) 7795,4020
GND on Bottom Layer "GND_L06_P290" (solid, pour order 290): 7413.72,4236.18 7413.72,4155 7525,4155 7525,4236.18
GND on Bottom Layer "GND_L06_P515" (solid, pour order 515): 7430,3935 7430,3775 7535,3775 7535,3935
+3.3V on Bottom Layer "+3.3V_L06_P306" (solid, pour order 306): 7605,3830 7605,3910 7585,3910 7585,4065 7430,4065 7430,3945 7540,3945 7540,3830
-15V on Bottom Layer "Bottom Layer--15V" (solid, pour order 2402): 82 vertices, not listed, extent 2380,50 6680,2600
NetC185_1 on Bottom Layer "Bottom Layer-NetC187_1" (solid, pour order 2399): 6495,370 6495,425.05 ccw(c6460.02,425.02) 6460.05,460 6389.81,460 ccw(c6390,425) 6355,425 6355,410 6355,385 6443.54,385 6443.54,295 6365,295 6365,260 ccw(c6390,260) 6390,235 6460.03,235 ccw(c6459.96,270.04) 6495,270.04
+15V on Bottom Layer "Bottom Layer-+15V 3" (solid, pour order 2396): 6405,85 6405,125 6085,125 6085,84.91 ccw(c6120,85) 6120.45,50 6370.09,50 ccw(c6370,85)
GND on Bottom Layer "Bottom Layer-GND 7" (solid, pour order 2389): 5845,50 ccw(c5845,85) 5845.42,50 6035.2,50 ccw(c6035,85) 6070,85 6070,130 5810,130 5810,84.91 ccw(c5845,85)
NetC105_2 on Bottom Layer "Bottom Layer-NetC202_2" (solid, pour order 2382): 5840,500 5840,585 6070.07,585 ccw(c6070,610) 6095,610 6095,635 ccw(c6070,635) 6070,660 5850.1,660 ccw(c5850,645) 5835,645 cw(c5820,645) 5820,630 5750,630 5720,630 ccw(c5720,595) 5685,595 5685,499.85 ccw(c5720,500) 5720,465 5804.47,465 ccw(c5805,500)
NetC194_1 on Bottom Layer "Bottom Layer-NetC214_1" (solid, pour order 2369): 5685,254.88 ccw(c5720,255) 5719.87,220 5775.12,220 ccw(c5775.12,254.88) 5810,254.88 5810,295 5720,295 5720,380 5840,380 5840,419.56 ccw(c5804.67,419.67) 5804.56,455 5719.92,455 ccw(c5719.99,420.01) 5685,419.56
NetC107_2 on Bottom Layer "Bottom Layer-NetC186_2" (solid, pour order 2359): 6389.77,470 6460,470 ccw(c6460,505) 6495,505 6495,625.15 ccw(c6459.96,624.96) 6459.96,660 6360,660 6154.92,660 ccw(c6155,625) 6120,624.99 6120,599.88 ccw(c6155,600) 6155,565 6355,565 6355,504.88 ccw(c6390,505)
NetD18_2 on Bottom Layer "Bottom Layer-NetD18_2" (solid, pour order 1650): 18 vertices, not listed, extent 7470,1329.99 7950,1850
+12V on Bottom Layer "Bottom Layer-+12V 5" (solid, pour order 2340): 5825,680 5825,775 5825,1020.09 ccw(c5785,1020) 5790,1059.69 ccw(c5795,1020) 5755,1020 5755,925 5755,679.87 ccw(c5795,680) 5790,640.31 ccw(c5785,680)
GND on Bottom Layer "Bottom Layer-GND 8" (solid, pour order 2332): 5665,679.87 ccw(c5705,680) 5705,640 5705.16,640 ccw(c5705,680) 5745,680 5745,775 5745,1020.09 ccw(c5705,1020) 5705,1060 5704.84,1060 ccw(c5705,1020) 5665,1020 5665,925
VIN_MID on Bottom Layer "Bottom Layer-VIN_MID" (solid, pour order 1428): 17 vertices, not listed, extent 6715,365 6850,770
GND on Bottom Layer "NONET_L-01_P-001" (solid, pour order 2122): 6085,575 6085,310 5730,310 5730,370 5850,370 5850,575
+15V on Bottom Layer "NONET_L-01_P-001" (solid, pour order 2121): 6100,580 6100,305 6440,305 6440,375 6345,375 6345,580
GND on Bottom Layer "NONET_L-01_P-001" (solid, pour order 2126): 6405,140 6405,210 6360,210 6360,217.5 6360,295 6100,295 6100,140
VIN_PROTECT on Bottom Layer "Bottom Layer-VIN_PROTECT" (solid, pour order 1442): 7055,189.81 7055,545.19 ccw(c7020,545) 7020.17,580 6879.93,580 ccw(c6880.07,559.93) 6860,559.93 6860,190 ccw(c6895,190) 6895,155 7020.25,155 ccw(c7020,190)
+12V on Bottom Layer "Bottom Layer-+12V 4" (solid, pour order 1436): 6679.88,84.82 ccw(c6714.88,85) 6715,50 6810.07,50 ccw(c6809.98,84.91) 6844.88,84.82 6844.88,295.24 ccw(c6809.99,295.11) 6810.07,330 6714.69,330 ccw(c6714.88,295.01) 6679.88,295.24
U on Bottom Layer "Bottom Layer-U" (solid, pour order 809): 25 vertices, not listed, extent 1545,1000 2955,2845
W on Bottom Layer "Bottom Layer-W" (solid, pour order 806): 18 vertices, not listed, extent 4045,1000 4880,2845
V on Bottom Layer "Bottom Layer-V" (solid, pour order 780): 17 vertices, not listed, extent 2935,1000 3710,2845.01
NetC88_1 on Bottom Layer "NONET_L-01_P-001" (solid, pour order 974): 5535,1865 ccw(c5535,1820) 5490,1820 5490,1730 ccw(c5535,1730) 5535,1685 5715,1685 cw(c5715,1640) 5760,1640 5760,1635 ccw(c5805,1635) 5805,1590 5925,1590 ccw(c5925,1635) 5970,1635 5970,1645.83 cw(c6004.58,1650.42) 6000,1685 ccw(c5992.08,1717.08) 6025,1720 6025,1820 ccw(c5980,1820) 5980,1865
-3V_W_HS on Bottom Layer "Bottom Layer--3V_W_HS" (solid, pour order 2026): 5210,3275 5220,3275 ccw(c5220,3320) 5265,3320 5265,3615.28 ccw(c5220,3615) 5220.06,3660 5184.85,3660 ccw(c5185,3615) 5140,3615 5140,3560.13 ccw(c5165.05,3560.05) 5165.06,3535 cw(c5165,3515) 5185,3515 5185,3300 ccw(c5210,3300)
+15V_W_HS on Bottom Layer "Bottom Layer-+15V_W_HS" (solid, pour order 2025): 5040,3275 ccw(c5039.95,3320.05) 5085,3320 5085,3330 5010,3405 5010,3470.14 ccw(c4965,3470) 4965.14,3515 ccw(c4965.15,3469.85) 4920,3470 4920,3375 5020,3275
S6 on Bottom Layer "Bottom Layer-S6" (solid, pour order 2024): 31 vertices, not listed, extent 4770,2525 5265,3160
-3V_W_LS on Bottom Layer "Bottom Layer--3V_W_LS" (solid, pour order 2023): 5210,2525 5220,2525 ccw(c5220,2570) 5265,2570 5265,2865.28 ccw(c5220,2865) 5220.06,2910 5184.85,2910 ccw(c5185,2865) 5140,2865 5140,2810.13 ccw(c5165.05,2810.05) 5165.06,2785 cw(c5165,2765) 5185,2765 5185,2550 ccw(c5210,2550)
+15V_W_LS on Bottom Layer "Bottom Layer-+15V_W_LS" (solid, pour order 2022): 5040,2525 ccw(c5039.95,2570.05) 5085,2570 5085,2580 5010,2655 5010,2720.14 ccw(c4965,2720) 4965.14,2765 ccw(c4965.15,2719.85) 4920,2720 4920,2625 5020,2525
S4 on Bottom Layer "Bottom Layer-S4" (solid, pour order 2021): 31 vertices, not listed, extent 4770,1775 5265,2410
-3V_V_LS on Bottom Layer "Bottom Layer--3V_V_LS" (solid, pour order 2003): 5210,1775 5220,1775 ccw(c5220,1820) 5265,1820 5265,2115.28 ccw(c5220,2115) 5220.06,2160 5184.85,2160 ccw(c5185,2115) 5140,2115 5140,2060.13 ccw(c5165.05,2060.05) 5165.06,2035 cw(c5165,2015) 5185,2015 5185,1800 ccw(c5210,1800)
+15V_V_LS on Bottom Layer "Bottom Layer-+15V_V_LS" (solid, pour order 1997): 5040,1775 ccw(c5039.95,1820.05) 5085,1820 5085,1830 5010,1905 5010,1970.14 ccw(c4965,1970) 4965.14,2015 ccw(c4965.15,1969.85) 4920,1970 4920,1875 5020,1775
S1 on Bottom Layer "Bottom Layer-S2" (solid, pour order 1852): 21 vertices, not listed, extent 1830,2680 2225.07,3130
-3V_U_HS on Bottom Layer "Bottom Layer--3V_U_LS" (solid, pour order 1851): 1735,2724.9 ccw(c1780,2725) 1777.5,2680.07 ccw(c1775,2725) 1820,2724.91 1820,2765.4 1820.37,2765.77 cw(c1865,2760) 1859.85,2804.7 ccw(c1859.7,2850) 1905,2849.91 1905,3085.14 ccw(c1860,3085) 1860.23,3130 1779.81,3130 ccw(c1780,3085) 1735,3085 1735,2775
+15V_U_HS on Bottom Layer "Bottom Layer-+15V_U_LS" (solid, pour order 1850): 1980,2680 2005.11,2680 ccw(c2005,2725) 2050,2724.9 2050,2730.17 ccw(c2005,2730) 2005.11,2775 1979.86,2775 ccw(c1980,2730) 1935,2730 1935,2775 1935,2727.5 1935,2724.9 ccw(c1980,2725)
-3V_U_LS on Bottom Layer "Bottom Layer--3V_U_LS" (solid, pour order 1034): 1735,1974.9 ccw(c1780,1975) 1777.5,1930.07 ccw(c1775,1975) 1820,1974.91 1820,2015.4 1820.37,2015.77 cw(c1865,2010) 1859.85,2054.7 ccw(c1859.7,2100) 1905,2099.91 1905,2335.14 ccw(c1860,2335) 1860.23,2380 1779.81,2380 ccw(c1780,2335) 1735,2335 1735,2025
GND on Bottom Layer "Bottom Layer-GND 6" (solid, pour order 1667): 7470,1365 ccw(c7505,1365) 7505.14,1330 7600.14,1330 ccw(c7600,1365) 7635,1364.84 7635,1505.15 ccw(c7600,1505) 7600.18,1540 7504.81,1540 ccw(c7505,1505) 7470,1505
+12V on Bottom Layer "Bottom Layer-+12V 3" (solid, pour order 1659): 7875,1364.78 7875,1505.08 ccw(c7840,1505) 7840.15,1540 7789.82,1540 ccw(c7790,1505) 7755,1505.12 7755,1365 ccw(c7790,1365) 7789.87,1330 7840.18,1330 ccw(c7840,1365)
GND on Bottom Layer "Bottom Layer-GND 9" (solid, pour order 1451): 6969.99,50 ccw(c6969.89,75.11) 6995,74.99 6995,115.03 ccw(c6969.85,114.85) 6969.95,140 6884.96,140 ccw(c6885.06,114.94) 6860,114.94 6860,74.97 ccw(c6885.11,75.11) 6885.01,50
NetC87_2 on Bottom Layer "Bottom Layer-NetC157_2" (solid, pour order 1011): 24 vertices, not listed, extent 1025,1590 1515.4,2040
+15V on Bottom Layer "Bottom Layer-+15V" (solid, pour order 1419): 5370,1334.96 5370,1489.91 ccw(c5344.91,1489.91) 5344.98,1515 5304.95,1515 ccw(c5305.07,1489.93) 5280,1489.92 5280,1405 5280,1391.3 5280,1334.98 ccw(c5305.03,1335.03) 5304.94,1310 5344.97,1310 ccw(c5344.97,1335.03)
GND on Bottom Layer "Bottom Layer-GND" (solid, pour order 1130): 5505,1234.92 5505,1365.14 ccw(c5457.49,1367.5) 5460.08,1415 5425,1415 ccw(c5425.07,1369.93) 5380,1370 5380,1234.92 ccw(c5427.46,1237.47) 5429.85,1190 5460.08,1190 ccw(c5459.99,1235.01)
